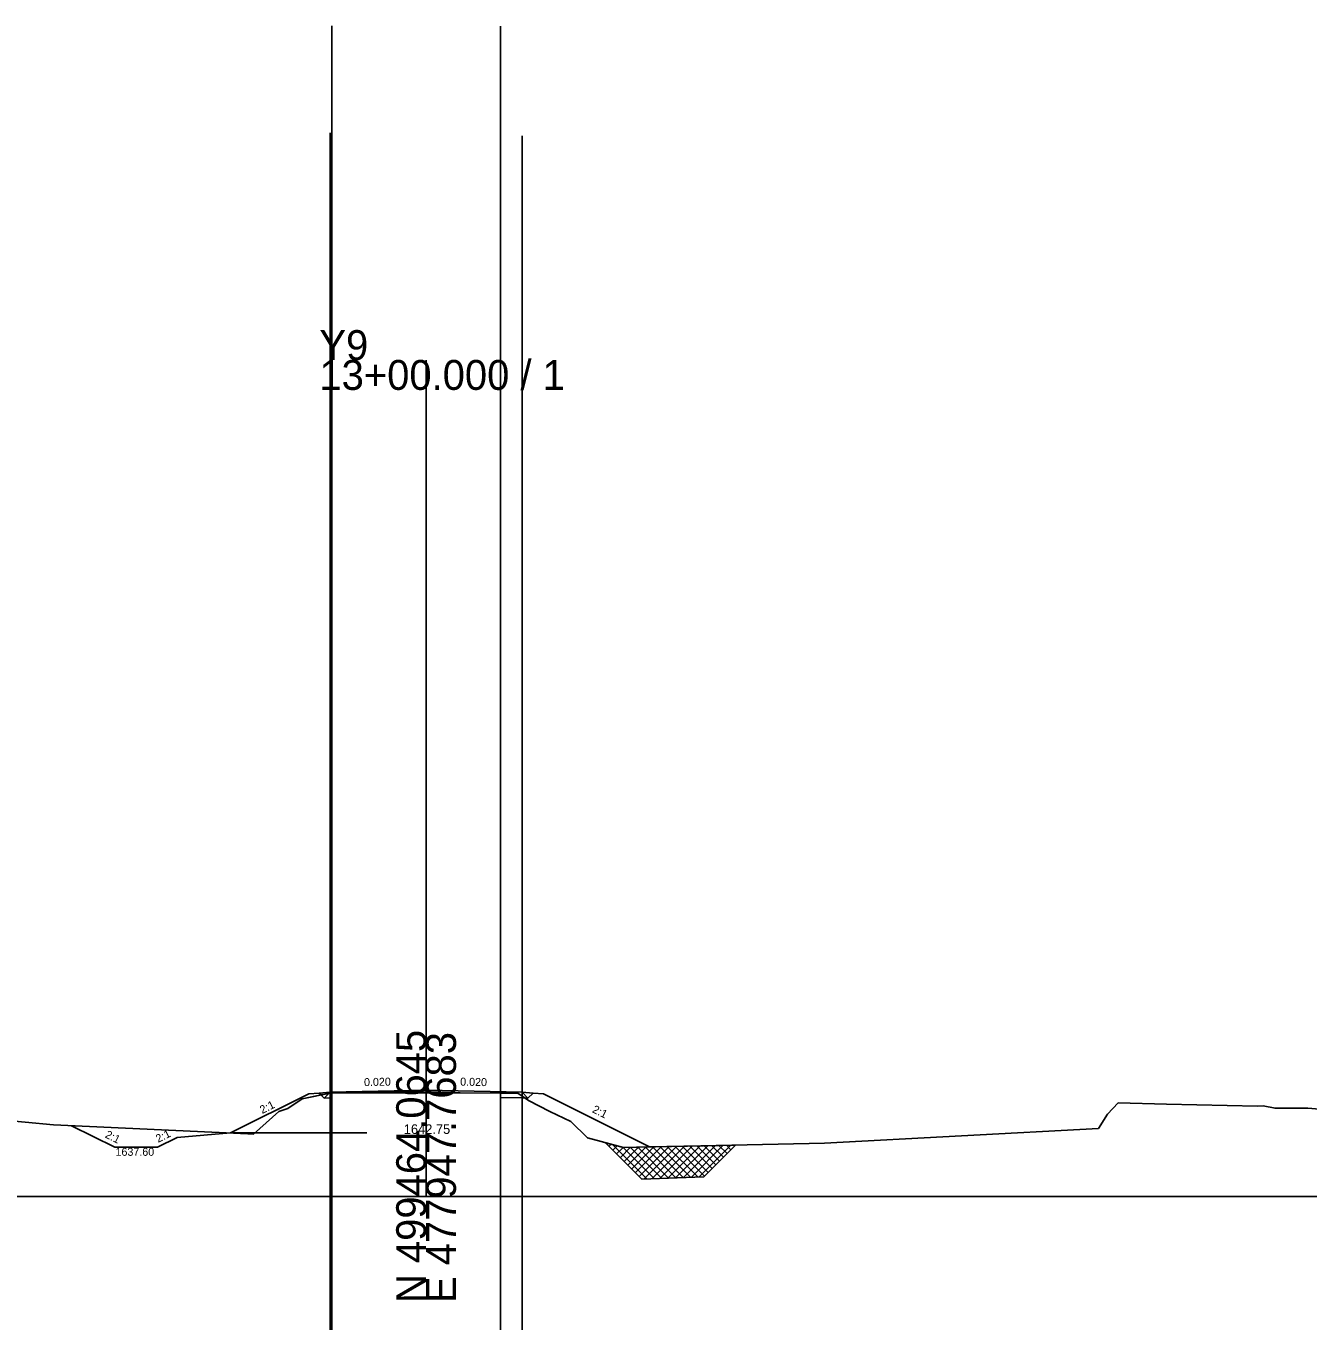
# Model space of a CAD drawing. Extents: x -26 to 403, y -99 to 4540.
# Drawn here: x 162.5 to 282.7, y 2988.3 to 3109.7 of the extents above; entities that cross this region are included whole.
import ezdxf

# ---------------------------------------------------------------- set-up
doc = ezdxf.new("R2010")
doc.units = 0
for name, color, linetype in [('Exist Cross Section Cell', 7, 'Continuous'), ('Exist XS Center Line Elevation Label', 7, 'Continuous'), ('Exist XS Ground Line', 7, 'Continuous'), ('Prop XS DDE', 7, 'Continuous'), ('Prop XS Ditch Slope Text', 7, 'Continuous'), ('Prop XS Ditch Standard Text', 7, 'Continuous'), ('Prop XS Dump Level', 7, 'Continuous'), ('Prop XS Earthwork Shape', 7, 'Continuous'), ('Prop XS EOT Tick Mark', 7, 'Continuous'), ('Prop XS Finish Grade', 7, 'Continuous'), ('Prop XS Finish Grade Earthwork', 7, 'Continuous'), ('Prop XS Finish Grade Pavement', 7, 'Continuous'), ('Prop XS Pvmt Edge Slope', 7, 'Continuous'), ('Prop XS SE Text', 7, 'Continuous'), ('Prop XS Shoulder Borrow Shape', 7, 'Continuous'), ('Prop XS Side Slope Text', 7, 'Continuous'), ('Prop XS Subgrade Earthwork', 7, 'Continuous'), ('Prop XS Undercut Exc', 7, 'Continuous'), ('Prop XS Undercut Exc Hatch', 7, 'Continuous'), ('Scratch_Level_1', 7, 'Continuous'), ('Scratch_Level_2', 7, 'Continuous'), ('Scratch_Level_6', 7, 'Continuous'), ('Scratch_Level_7', 7, 'Continuous')]:
    doc.layers.add(name, color=color, linetype=linetype)

msp = doc.modelspace()

# ---------------------------------------------------------------- linework, layer by layer
at = {"layer": 'Exist Cross Section Cell'}
for p, q in [((200, 3000), (200, 3078.39)), ((0, 3000), (200, 3000)), ((200, 3000), (400, 3000))]:
    msp.add_line(p, q, dxfattribs=at)
at = {"layer": 'Exist XS Ground Line'}
msp.add_lwpolyline([(159.74, 3007.21), (165.07, 3006.7), (183.28, 3005.86), (183.82, 3005.84), (186.21, 3007.95), (187.04, 3008.23), (188.4, 3009.15), (191.18, 3009.71), (196.69, 3009.75), (199.49, 3009.75), (200, 3009.75), (201.28, 3009.75), (203.19, 3009.71), (208.61, 3009.66), (209.61, 3008.98), (211.61, 3007.95), (213.57, 3007.01), (215.13, 3005.48), (218.49, 3004.58), (237.34, 3004.99), (263.01, 3006.36), (263.88, 3007.7), (264.85, 3008.76), (269.39, 3008.65), (277.91, 3008.45), (278.45, 3008.47), (279.57, 3008.25), (282.63, 3008.26), (288.05, 3007.8)], dxfattribs=at)
at = {"layer": 'Prop XS DDE'}
for p, q in [((166.78, 3006.62), (170.82, 3004.6)), ((176.66, 3005.52), (181.66, 3005.94)), ((174.82, 3004.6), (176.66, 3005.52)), ((174.82, 3004.6), (170.82, 3004.6))]:
    msp.add_line(p, q, dxfattribs=at)
at = {"layer": 'Prop XS Dump Level'}
for p, q in [((191, 3009.77), (200, 3009.95)), ((200, 3009.95), (209, 3009.77))]:
    msp.add_line(p, q, dxfattribs=at)
at = {"layer": 'Prop XS Earthwork Shape'}
for points in [[(189, 3009.61), (181.66, 3005.94), (183.28, 3005.86), (183.82, 3005.84), (186.21, 3007.95), (187.04, 3008.23), (188.4, 3009.15), (190.16, 3009.5), (189.98, 3009.68)], [(190.45, 3009.21), (190.16, 3009.5), (191.18, 3009.71), (191.18, 3009.23), (191, 3009.22)], [(208.61, 3009.66), (209.26, 3009.22), (209, 3009.22), (206.96, 3009.27), (206.96, 3009.68)], [(211, 3009.61), (220.94, 3004.64), (218.49, 3004.58), (215.13, 3005.48), (213.57, 3007.01), (211.61, 3007.95), (209.61, 3008.98), (209.26, 3009.22), (209.55, 3009.21), (210.02, 3009.68)]]:
    msp.add_lwpolyline(points, close=True, dxfattribs=at)
at = {"layer": 'Prop XS EOT Tick Mark'}
for p, q in [((191, 3009.77), (191, 3010.77)), ((209, 3009.77), (209, 3010.77))]:
    msp.add_line(p, q, dxfattribs=at)
at = {"layer": 'Prop XS Finish Grade'}
for p, q in [((191, 3009.77), (189.98, 3009.68)), ((209, 3009.77), (210.02, 3009.68))]:
    msp.add_line(p, q, dxfattribs=at)
at = {"layer": 'Prop XS Finish Grade Earthwork'}
for p, q in [((189, 3009.61), (181.66, 3005.94)), ((189.98, 3009.68), (189, 3009.61)), ((210.02, 3009.68), (211, 3009.61)), ((211, 3009.61), (220.94, 3004.64))]:
    msp.add_line(p, q, dxfattribs=at)
at = {"layer": 'Prop XS Finish Grade Pavement'}
for p, q in [((191, 3009.77), (200, 3009.95)), ((200, 3009.95), (209, 3009.77))]:
    msp.add_line(p, q, dxfattribs=at)
at = {"layer": 'Prop XS Pvmt Edge Slope'}
for p, q in [((191, 3009.77), (190.45, 3009.21)), ((209, 3009.77), (209.55, 3009.21))]:
    msp.add_line(p, q, dxfattribs=at)
at = {"layer": 'Prop XS Shoulder Borrow Shape'}
for points in [[(191, 3009.77), (189.98, 3009.68), (190.45, 3009.21)], [(209, 3009.77), (210.02, 3009.68), (209.55, 3009.21)]]:
    msp.add_lwpolyline(points, close=True, dxfattribs=at)
at = {"layer": 'Prop XS Subgrade Earthwork'}
for p, q in [((190.45, 3009.21), (189.98, 3009.68)), ((191.18, 3009.23), (191.18, 3009.71)), ((206.96, 3009.27), (206.96, 3009.68)), ((209.55, 3009.21), (210.02, 3009.68)), ((191, 3009.22), (190.45, 3009.21)), ((191.18, 3009.23), (191, 3009.22)), ((209, 3009.22), (206.96, 3009.27)), ((209, 3009.22), (209.55, 3009.21))]:
    msp.add_line(p, q, dxfattribs=at)
at = {"layer": 'Prop XS Undercut Exc'}
msp.add_line((226.03, 3001.84), (229.01, 3004.81), dxfattribs=at)
for points in [[(216.81, 3005.03), (220.22, 3001.62), (226.03, 3001.84)], [(229.01, 3004.81), (218.49, 3004.58), (216.81, 3005.03)]]:
    msp.add_lwpolyline(points, dxfattribs=at)
at = {"layer": 'Prop XS Undercut Exc Hatch'}
for p, q in [((217.15, 3004.69), (217.34, 3004.89)), ((217.47, 3004.86), (220.69, 3001.64)), ((217.5, 3004.34), (217.9, 3004.74)), ((219.62, 3002.22), (222.06, 3004.66)), ((219.98, 3001.87), (222.79, 3004.68)), ((220.45, 3001.63), (223.51, 3004.69)), ((221.18, 3001.66), (224.23, 3004.71)), ((221.91, 3004.66), (224.78, 3001.79)), ((221.92, 3001.68), (224.96, 3004.72)), ((222.6, 3004.67), (225.46, 3001.82)), ((222.65, 3001.71), (225.68, 3004.74)), ((223.3, 3004.69), (226.09, 3001.89)), ((223.39, 3001.74), (226.4, 3004.75)), ((223.99, 3004.7), (226.44, 3002.25)), ((224.12, 3001.77), (227.12, 3004.77)), ((224.68, 3004.72), (226.8, 3002.6)), ((224.86, 3001.79), (227.85, 3004.79)), ((225.37, 3004.73), (227.15, 3002.95)), ((225.59, 3001.82), (228.57, 3004.8)), ((226.06, 3004.75), (227.5, 3003.31)), ((226.76, 3004.76), (227.86, 3003.66)), ((227.45, 3004.78), (228.21, 3004.02)), ((228.14, 3004.79), (228.56, 3004.37)), ((228.83, 3004.81), (228.92, 3004.72)), ((217.86, 3003.99), (218.46, 3004.59)), ((218.21, 3003.63), (219.17, 3004.6)), ((218.44, 3004.6), (221.37, 3001.66)), ((218.56, 3003.28), (219.9, 3004.61)), ((218.92, 3002.93), (220.62, 3004.63)), ((219.14, 3004.6), (222.05, 3001.69)), ((219.27, 3002.57), (221.34, 3004.64)), ((219.84, 3004.61), (222.73, 3001.71)), ((220.53, 3004.63), (223.41, 3001.74)), ((221.22, 3004.64), (224.1, 3001.77))]:
    msp.add_line(p, q, dxfattribs=at)
at = {"layer": 'Scratch_Level_1'}
for p, q in [((191.18, 3109.71), (191.18, 2909.71)), ((206.96, 3109.68), (206.96, 2909.68))]:
    msp.add_line(p, q, dxfattribs=at)
at = {"layer": 'Scratch_Level_2'}
for p, q in [((218.49, 3004.58), (216.81, 3005.03)), ((226.03, 3001.84), (229.01, 3004.81))]:
    msp.add_line(p, q, dxfattribs=at)
for points in [[(216.81, 3005.03), (220.22, 3001.62), (226.03, 3001.84)], [(229.01, 3004.81), (220.94, 3004.64), (218.49, 3004.58)]]:
    msp.add_lwpolyline(points, dxfattribs=at)
at = {"layer": 'Scratch_Level_6'}
for p, q in [((191, 3099.67), (191, 2949.67)), ((209, 3099.4), (209, 2949.4)), ((191.18, 3009.71), (206.96, 3009.68))]:
    msp.add_line(p, q, dxfattribs=at)
at = {"layer": 'Scratch_Level_7'}
msp.add_line((181.66, 3005.94), (194.46, 3005.94), dxfattribs=at)

# ---------------------------------------------------------------- texts
at = {"layer": 'Exist Cross Section Cell'}
for s, p in [('Y9', (190, 3078.39)), ('13+00.000 / 1', (190, 3075.59))]:
    msp.add_text(s, height=2.8, dxfattribs=at).set_placement(p)
for s, p in [('N 499464.0645', (200, 2990)), ('E 477947.7683', (202.8, 2990))]:
    msp.add_text(s, height=2.8, rotation=90, dxfattribs=at).set_placement(p)
at = {"layer": 'Exist XS Center Line Elevation Label'}
msp.add_text('1642.75', height=0.9, dxfattribs=at).set_placement((197.91, 3005.85))
at = {"layer": 'Prop XS Ditch Slope Text'}
msp.add_text('2:1', height=0.75, rotation=26.5651, dxfattribs=at).set_placement((174.89, 3005.01))
at = {"layer": 'Prop XS Ditch Standard Text'}
msp.add_text('1637.60', height=0.75, dxfattribs=at).set_placement((170.89, 3003.8))
at = {"layer": 'Prop XS Dump Level'}
for p in [(189, 3009.57), (211, 3009.57)]:
    msp.add_text('Case1', height=0.04, dxfattribs=at).set_placement(p)
at = {"layer": 'Prop XS SE Text'}
for rotation, p in [(1.1458, (194.19, 3010.33)), (358.8542, (203.19, 3010.38))]:
    msp.add_text('0.020', height=0.75, rotation=rotation, dxfattribs=at).set_placement(p)
at = {"layer": 'Prop XS Side Slope Text'}
for rotation, p in [(26.5651, (184.64, 3007.72)), (333.4349, (215.51, 3007.91)), (333.416, (169.85, 3005.55))]:
    msp.add_text('2:1', height=0.75, rotation=rotation, dxfattribs=at).set_placement(p)

doc.saveas('drawing.dxf')
